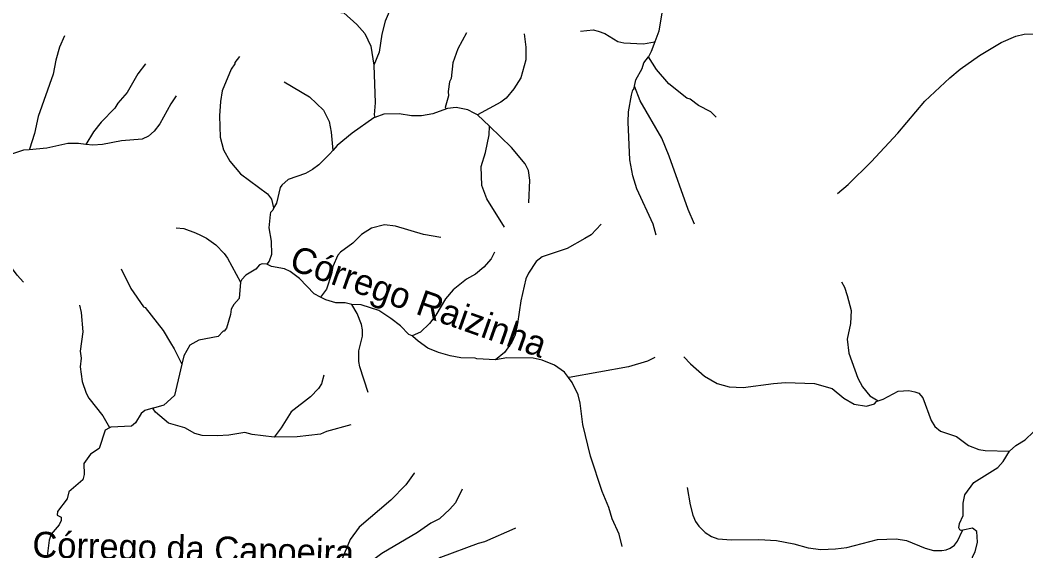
# Model space of a CAD drawing. Extents: x 393 to 446.6, y 8175.5 to 8231.
# Drawn here: x 415.52 to 421.76, y 8189.58 to 8192.87 of the extents above; entities that cross this region are included whole.
import ezdxf
from ezdxf.enums import TextEntityAlignment as Align

# ---------------------------------------------------------------- set-up
doc = ezdxf.new("R2010")
doc.units = 0
doc.header["$LTSCALE"] = 0.064
doc.linetypes.add('LONG_DASHED', pattern=[7.5, 6, -1.5])
doc.layers.add('61', color=7, linetype='Continuous')
doc.layers.add('7', color=7, linetype='Continuous', lineweight=25)
doc.layers.add('9', color=7, linetype='LONG_DASHED', lineweight=25)

msp = doc.modelspace()

# ---------------------------------------------------------------- linework, layer by layer
at = {"layer": '7'}
for points in [[(419.4591, 8192.7358), (419.4838, 8192.8026), (419.5225, 8193.0239), (419.5355, 8193.153), (419.5664, 8193.2948)], [(420.5921, 8191.7925), (420.6578, 8191.8483), (420.8015, 8191.9904), (420.9662, 8192.168), (421.1341, 8192.3666), (421.2892, 8192.5119), (421.3537, 8192.5652), (421.4732, 8192.6492), (421.6089, 8192.7299), (421.6993, 8192.7703), (421.751, 8192.7816), (421.99, 8192.7881), (422.0675, 8192.8155), (422.1164, 8192.8429), (422.1165, 8192.8429)], [(418.9953, 8192.8015), (419.0737, 8192.8091), (419.106, 8192.801), (419.1479, 8192.7864), (419.2287, 8192.7364), (419.2642, 8192.7283), (419.3869, 8192.7219), (419.4556, 8192.7351), (419.4591, 8192.7358)], [(415.7924, 8192.771), (415.7601, 8192.7009), (415.7375, 8192.6202), (415.7213, 8192.533), (415.6277, 8192.2714), (415.6051, 8192.1648), (415.5735, 8192.0685), (415.5722, 8192.0646)], [(419.4184, 8192.641), (419.4211, 8192.6445), (419.4374, 8192.6771), (419.4591, 8192.7358)], [(416.2953, 8192.5976), (416.2461, 8192.5362), (416.1799, 8192.4199), (416.1218, 8192.3537), (416.104, 8192.323), (416.0185, 8192.2358), (415.9716, 8192.1761), (415.9241, 8192.0985)], [(419.3311, 8192.4594), (419.3394, 8192.4985), (419.3784, 8192.5689), (419.3901, 8192.604), (419.4184, 8192.641)], [(419.8389, 8192.2673), (419.8063, 8192.2999), (419.7293, 8192.3392), (419.6776, 8192.3795), (419.6566, 8192.386), (419.5452, 8192.4748), (419.4676, 8192.562), (419.4184, 8192.641)], [(416.4856, 8192.399), (416.4512, 8192.3489), (416.3834, 8192.2262), (416.3479, 8192.1793), (416.3123, 8192.1502), (416.2736, 8192.1309), (416.1444, 8192.1195), (416.0282, 8192.0985), (415.9668, 8192.0937), (415.9241, 8192.0985)], [(419.4655, 8191.5357), (419.4467, 8191.6028), (419.3449, 8191.8225), (419.3207, 8191.9032), (419.3029, 8192.0033), (419.2916, 8192.2358), (419.2948, 8192.3004), (419.3126, 8192.4038), (419.3207, 8192.4377), (419.3272, 8192.4409), (419.3311, 8192.4594)], [(419.7049, 8191.6037), (419.6636, 8191.6951), (419.5466, 8192.025), (419.5006, 8192.1361), (419.3659, 8192.3683), (419.3313, 8192.4589), (419.3311, 8192.4594)], [(415.9241, 8192.0985), (415.8783, 8192.1036), (415.8118, 8192.1034), (415.6826, 8192.0743), (415.5722, 8192.0646)], [(415.5722, 8192.0646), (415.5363, 8192.0615), (415.4307, 8192.0275), (415.276, 8191.9404)], [(415.5374, 8191.2438), (415.4969, 8191.2863), (415.4371, 8191.3671), (415.3564, 8191.4898), (415.3095, 8191.577), (415.2805, 8191.6626), (415.2514, 8191.7223), (415.1949, 8191.7918), (415.1027, 8191.8573)], [(420.6166, 8191.2452), (420.6352, 8191.2115), (420.6529, 8191.1604), (420.6771, 8191.0667), (420.6723, 8190.986), (420.6529, 8190.8891), (420.6626, 8190.8019), (420.7175, 8190.6469), (420.7466, 8190.5936), (420.7934, 8190.537), (420.8437, 8190.5072), (420.8447, 8190.5066)], [(419.6386, 8190.7794), (419.6792, 8190.7357), (419.7664, 8190.6598), (419.8455, 8190.6146), (419.9198, 8190.5936), (420.007, 8190.5887), (420.1943, 8190.6146), (420.2686, 8190.6194), (420.4495, 8190.6146), (420.5593, 8190.5823), (420.6319, 8190.5241), (420.6949, 8190.4854), (420.7724, 8190.4741), (420.8209, 8190.4886), (420.8338, 8190.5031), (420.8447, 8190.5066)], [(420.8447, 8190.5066), (420.8751, 8190.5165), (420.9694, 8190.5661), (421.034, 8190.571), (421.0728, 8190.5629), (421.097, 8190.5548), (421.1212, 8190.5257), (421.1745, 8190.3853), (421.1971, 8190.3481), (421.231, 8190.3174), (421.3311, 8190.2851), (421.4054, 8190.2302), (421.47, 8190.2044), (421.5088, 8190.1979), (421.6596, 8190.1935)], [(421.6596, 8190.1935), (421.6993, 8190.2286), (421.7574, 8190.2642), (421.8091, 8190.3142)], [(421.3697, 8189.7036), (421.3604, 8189.7016), (421.3511, 8189.7051), (421.3452, 8189.7179), (421.3487, 8189.7458), (421.3715, 8189.7943), (421.3715, 8189.8718), (421.3828, 8189.9235), (421.4393, 8189.9993), (421.5878, 8190.093), (421.6218, 8190.1301), (421.6596, 8190.1935)], [(419.6584, 8189.9678), (419.6776, 8189.8621), (419.6937, 8189.7975), (419.7099, 8189.7587), (419.7309, 8189.728), (419.7696, 8189.6893), (419.81, 8189.6651), (419.8488, 8189.6505), (419.9327, 8189.6441), (420.1039, 8189.6457), (420.2137, 8189.6392), (420.3203, 8189.6198), (420.4107, 8189.594), (420.4882, 8189.5843), (420.5786, 8189.5876), (420.6497, 8189.5972), (420.8402, 8189.6457), (420.9565, 8189.6505), (421.0211, 8189.6392), (421.1374, 8189.5924), (421.189, 8189.5779), (421.2407, 8189.5779), (421.2665, 8189.5811), (421.2924, 8189.5924), (421.3182, 8189.6118), (421.3376, 8189.636), (421.3689, 8189.7019), (421.3697, 8189.7036)], [(421.497, 8189.4318), (421.4981, 8189.4563), (421.4935, 8189.4725), (421.4829, 8189.481), (421.4344, 8189.5052), (421.4312, 8189.5375), (421.4474, 8189.5698), (421.4619, 8189.6296), (421.4571, 8189.6957), (421.4313, 8189.7168), (421.3697, 8189.7036)]]:
    msp.add_lwpolyline(points, dxfattribs=at)
at = {"layer": '9'}
msp.add_line((418.4301, 8192.2113), (418.3572, 8192.2813), dxfattribs=at)
for points in [[(417.8505, 8193.4243), (417.8593, 8193.3662), (417.8852, 8193.2806), (417.9126, 8193.1498), (417.8949, 8193.0674), (417.8238, 8192.9593), (417.7834, 8192.8624), (417.7624, 8192.7816), (417.7463, 8192.6702), (417.7127, 8192.589)], [(417.0401, 8193.1595), (417.06, 8193.1478), (417.1165, 8193.1353), (417.2748, 8193.082), (417.3345, 8193.0545), (417.5105, 8192.9173), (417.5251, 8192.9141), (417.6074, 8192.843), (417.6559, 8192.7865), (417.693, 8192.7074), (417.7127, 8192.589)], [(418.2873, 8192.7901), (418.2339, 8192.6912), (418.2033, 8192.604), (418.192, 8192.5071), (418.1823, 8192.4861), (418.1742, 8192.4264), (418.1758, 8192.3989), (418.1548, 8192.3279), (418.1633, 8192.3191)], [(418.6454, 8192.7852), (418.657, 8192.7025), (418.6554, 8192.6234), (418.6247, 8192.512), (418.5827, 8192.4425), (418.5343, 8192.386), (418.5004, 8192.3601), (418.3572, 8192.2813)], [(416.8789, 8192.6434), (416.8485, 8192.606), (416.8484, 8192.5976), (416.8258, 8192.5653), (416.7709, 8192.4296), (416.7596, 8192.365), (416.7548, 8192.2746), (416.758, 8192.1438), (416.779, 8192.0647), (416.8177, 8191.9936), (416.884, 8191.9145), (417.0519, 8191.7918), (417.0777, 8191.7578), (417.0896, 8191.7051), (417.0903, 8191.7019)], [(417.7127, 8192.589), (417.7204, 8192.3553), (417.714, 8192.2811), (417.7186, 8192.2649)], [(417.1566, 8192.4866), (417.3135, 8192.3924), (417.3991, 8192.3101), (417.4346, 8192.2407), (417.4475, 8192.1745), (417.4576, 8192.0607), (417.4576, 8192.0602)], [(418.1633, 8192.3191), (418.0789, 8192.2875), (418.0079, 8192.2746), (417.9465, 8192.2762), (417.8706, 8192.2875), (417.7754, 8192.2859), (417.7186, 8192.2649)], [(418.3572, 8192.2813), (418.3357, 8192.2919), (418.2953, 8192.3117), (418.2243, 8192.3262), (418.1693, 8192.3214), (418.1633, 8192.3191)], [(417.7186, 8192.2649), (417.7133, 8192.263), (417.5783, 8192.168), (417.4847, 8192.0921), (417.4576, 8192.0602)], [(418.5233, 8191.5848), (418.4148, 8191.7594), (418.3825, 8191.8434), (418.3793, 8191.9613), (418.4067, 8192.0469), (418.4277, 8192.1583), (418.4301, 8192.2113)], [(418.6756, 8191.7347), (418.6806, 8191.8754), (418.6724, 8191.9361), (418.6526, 8191.978), (418.5674, 8192.0795), (418.4301, 8192.2113)], [(417.4576, 8192.0602), (417.4395, 8192.0388), (417.37, 8191.971), (417.3313, 8191.9419), (417.2877, 8191.9177), (417.1795, 8191.8806), (417.1407, 8191.845), (417.131, 8191.8305), (417.1071, 8191.7343), (417.0903, 8191.7019)], [(417.0903, 8191.7019), (417.0842, 8191.69), (417.0697, 8191.6755), (417.0683, 8191.6621), (417.06, 8191.5802), (417.0745, 8191.4979), (417.0777, 8191.4155), (417.0616, 8191.3735), (417.0471, 8191.3557)], [(418.1282, 8191.5195), (418.0208, 8191.5382), (417.8464, 8191.5915), (417.7786, 8191.598), (417.6979, 8191.5786), (417.6353, 8191.5389), (417.5816, 8191.4849), (417.5057, 8191.43), (417.4888, 8191.4108), (417.4573, 8191.3396), (417.4491, 8191.2941), (417.4187, 8191.1996), (417.3814, 8191.1505), (417.3811, 8191.1501)], [(419.1251, 8191.6022), (419.062, 8191.5369), (419.0235, 8191.5135), (418.9122, 8191.4527), (418.7572, 8191.3994), (418.72, 8191.3719), (418.6732, 8191.2993), (418.657, 8191.2637), (418.6247, 8191.1281), (418.6053, 8190.986), (418.5892, 8190.9165), (418.5699, 8190.8716), (418.5244, 8190.8063), (418.4682, 8190.7617)], [(416.4844, 8191.5805), (416.5322, 8191.5758), (416.6046, 8191.5495), (416.6368, 8191.5338), (416.6741, 8191.5156), (416.7306, 8191.4753), (416.7839, 8191.4204), (416.8032, 8191.3913), (416.8836, 8191.2426)], [(418.4626, 8191.429), (418.4406, 8191.3881), (418.3954, 8191.3364), (418.3437, 8191.2928), (418.2889, 8191.2621), (418.2049, 8191.1959), (418.1581, 8191.1394), (418.0967, 8191.0377), (418.0579, 8190.9876), (418.0014, 8190.9327), (417.9497, 8190.9091)], [(417.0471, 8191.3557), (417.0185, 8191.3574), (417.0022, 8191.3505), (416.9788, 8191.3236), (416.9181, 8191.2863), (416.893, 8191.2601), (416.8836, 8191.2426)], [(417.3811, 8191.1501), (417.3429, 8191.1703), (417.2505, 8191.2669), (417.1924, 8191.3089), (417.1569, 8191.3251), (417.0777, 8191.3412), (417.0471, 8191.3557)], [(416.1427, 8191.3255), (416.2025, 8191.204), (416.2817, 8191.0909), (416.293, 8191.0861), (416.4044, 8190.944), (416.45, 8190.8668), (416.4722, 8190.8293), (416.5185, 8190.7374), (416.5201, 8190.7342)], [(416.8836, 8191.2426), (416.8766, 8191.1411), (416.842, 8191.1038), (416.8258, 8191.0748), (416.8226, 8191.0425), (416.7968, 8190.9585), (416.7823, 8190.9391), (416.7758, 8190.9391), (416.7451, 8190.9069), (416.6256, 8190.8826), (416.5707, 8190.8519), (416.5319, 8190.7858), (416.5201, 8190.7342)], [(417.5767, 8191.1039), (417.5335, 8191.1144), (417.4766, 8191.1152), (417.4136, 8191.1329), (417.3811, 8191.1501)], [(415.8839, 8191.1014), (415.8944, 8191.0548), (415.9054, 8190.9359), (415.8893, 8190.8148), (415.8941, 8190.7712), (415.8877, 8190.7179), (415.9006, 8190.6275), (415.9264, 8190.5532), (415.9425, 8190.5242), (416.0297, 8190.4144), (416.07, 8190.3409), (416.071, 8190.339)], [(417.6763, 8190.5579), (417.6252, 8190.7179), (417.6203, 8190.7502), (417.6203, 8190.8164), (417.6429, 8190.9085), (417.6413, 8190.9472), (417.6349, 8190.9811), (417.609, 8191.049), (417.5767, 8191.1039)], [(417.9497, 8190.9091), (417.9304, 8190.9181), (417.8771, 8190.9714), (417.8189, 8191.0183), (417.7431, 8191.0683), (417.6333, 8191.1022), (417.5767, 8191.1039)], [(418.4682, 8190.7617), (418.3527, 8190.7664), (418.3421, 8190.7712), (418.2517, 8190.7744), (418.1855, 8190.7857), (418.1145, 8190.8067), (418.0482, 8190.8342), (417.9885, 8190.8762), (417.9546, 8190.9068), (417.9497, 8190.9091)], [(419.458, 8190.7747), (419.4113, 8190.7537), (419.2949, 8190.7179), (418.9251, 8190.6519), (418.9214, 8190.6512)], [(416.5201, 8190.7342), (416.4754, 8190.5387), (416.4076, 8190.4805), (416.3431, 8190.4615), (416.3405, 8190.4608)], [(418.9214, 8190.6512), (418.896, 8190.6846), (418.8347, 8190.7276), (418.7572, 8190.7599), (418.7023, 8190.7712), (418.5375, 8190.7744), (418.4682, 8190.7617)], [(417.4018, 8190.6656), (417.3878, 8190.613), (417.3684, 8190.5839), (417.3184, 8190.5322), (417.1989, 8190.4385), (417.1375, 8190.3384), (417.0927, 8190.2815)], [(419.2552, 8189.6018), (419.2351, 8189.6796), (419.1931, 8189.7749), (419.1721, 8189.8443), (419.1302, 8189.9444), (419.0575, 8190.1624), (419.0106, 8190.3595), (418.9945, 8190.4919), (418.9816, 8190.5435), (418.9444, 8190.621), (418.9214, 8190.6512)], [(416.3405, 8190.4608), (416.2913, 8190.4463), (416.268, 8190.4288), (416.233, 8190.3693), (416.2067, 8190.3489), (416.0783, 8190.3431), (416.071, 8190.339)], [(417.0927, 8190.2815), (416.9566, 8190.2981), (416.9114, 8190.3094), (416.8129, 8190.2932), (416.7403, 8190.2884), (416.6466, 8190.2916), (416.6014, 8190.3045), (416.5384, 8190.3384), (416.4367, 8190.3675), (416.3575, 8190.4353), (416.3426, 8190.4576), (416.3405, 8190.4608)], [(416.071, 8190.339), (416.0439, 8190.3239), (416.0065, 8190.2107), (415.9522, 8190.1754), (415.9119, 8190.1172), (415.9135, 8190.0494), (415.9054, 8190.0155), (415.8182, 8189.9428), (415.8085, 8189.8992), (415.7472, 8189.8201), (415.7455, 8189.7975), (415.7713, 8189.7849), (415.7713, 8189.7639), (415.7573, 8189.7371), (415.7095, 8189.6799), (415.6966, 8189.6426), (415.6861, 8189.5586), (415.6889, 8189.5437)], [(417.569, 8190.3584), (417.4184, 8190.3164), (417.3816, 8190.3007), (417.2369, 8190.2832), (417.0927, 8190.2815)], [(417.9643, 8190.06), (417.9619, 8190.0567), (417.911, 8189.9848), (417.8173, 8189.8911), (417.6219, 8189.7232), (417.5654, 8189.6457), (417.4945, 8189.4761), (417.4516, 8189.4067)], [(418.2612, 8189.9581), (418.2191, 8189.8742), (418.1853, 8189.8333), (418.1211, 8189.7738), (418.0657, 8189.7476), (417.9839, 8189.6904), (417.7624, 8189.5585), (417.5813, 8189.4237), (417.4843, 8189.3985), (417.4817, 8189.3978)], [(418.5923, 8189.7154), (418.5877, 8189.7134), (418.3987, 8189.6311), (418.3599, 8189.6215), (418.1274, 8189.5343), (418.066, 8189.4987), (418.0224, 8189.4665), (417.9433, 8189.3825), (417.8672, 8189.2751), (417.8089, 8189.2156), (417.7981, 8189.1861)]]:
    msp.add_lwpolyline(points, dxfattribs=at)

# ---------------------------------------------------------------- texts
at = {"layer": '61'}
for s, rotation, p in [('Córrego Raizinha', 340.597, (417.9648, 8191.0485)), ('Córrego da Capoeira', 358.492, (416.5892, 8189.5095))]:
    msp.add_text(s, height=0.16, rotation=rotation, dxfattribs=at).set_placement(p, align=Align.CENTER)

doc.saveas('drawing.dxf')
